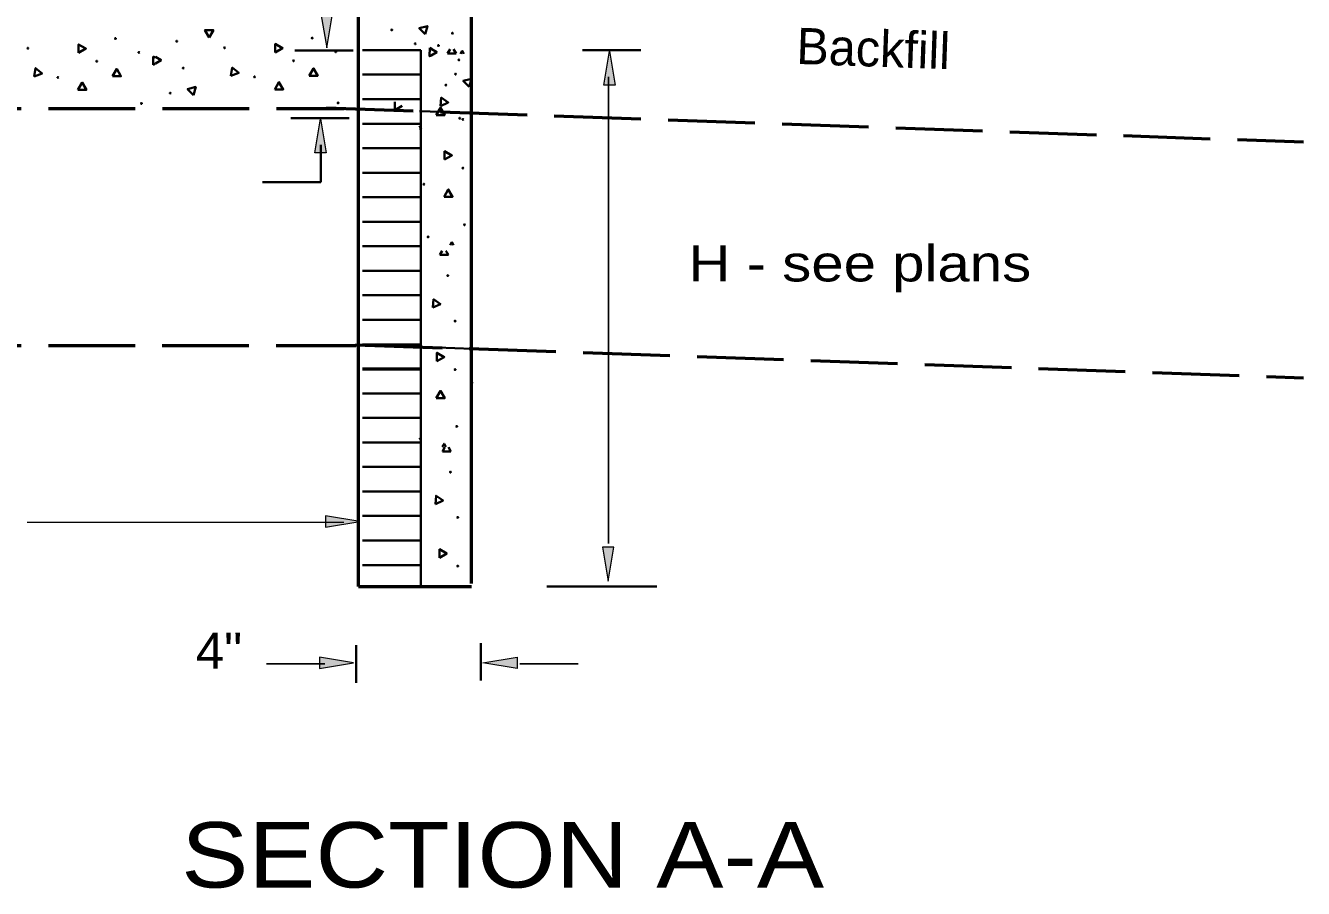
# Model space of a CAD drawing. Extents: x 72.6 to 107.3, y 36.1 to 58.1.
# Drawn here: x 92.859 to 97.548, y 50.456 to 53.623 of the extents above; entities that cross this region are included whole.
import ezdxf

# ---------------------------------------------------------------- set-up
doc = ezdxf.new("R2010")
doc.units = 0
doc.header["$LTSCALE"] = 0.053
doc.linetypes.add('LONG_DASHED', pattern=[7.5, 6, -1.5])
doc.layers.add('1', color=7, linetype='Continuous', lineweight=35)
doc.layers.add('3', color=7, linetype='Continuous', lineweight=13)

msp = doc.modelspace()

# ---------------------------------------------------------------- hatches: boundary and pattern name
at = {"layer": '3'}
for points in [[(93.98483, 53.66683), (93.94317, 53.66683), (93.964, 53.54183), (93.964, 53.54183)], [(95.02225, 53.40433), (94.98058, 53.40433), (95.00142, 53.52933), (95.00142, 53.52933)], [(93.962, 53.15625), (93.92033, 53.15625), (93.94117, 53.28125), (93.94117, 53.28125)], [(93.962, 53.15625), (93.92033, 53.15625), (93.94117, 53.28125), (93.94117, 53.28125)], [(93.96017, 51.82333), (93.96017, 51.78167), (94.08517, 51.8025), (94.08517, 51.8025)], [(93.96017, 51.82333), (93.96017, 51.78167), (94.08517, 51.8025), (94.08517, 51.8025)], [(95.01725, 51.70867), (94.97558, 51.70867), (94.99642, 51.58367), (94.99642, 51.58367)], [(95.01725, 51.70867), (94.97558, 51.70867), (94.99642, 51.58367), (94.99642, 51.58367)], [(93.93733, 51.30508), (93.93733, 51.26342), (94.06233, 51.28425), (94.06233, 51.28425)], [(93.93733, 51.30508), (93.93733, 51.26342), (94.06233, 51.28425), (94.06233, 51.28425)], [(94.6625, 51.30508), (94.6625, 51.26342), (94.5375, 51.28425), (94.5375, 51.28425)], [(94.6625, 51.30508), (94.6625, 51.26342), (94.5375, 51.28425), (94.5375, 51.28425)]]:
    msp.add_hatch(color=256, dxfattribs=at).paths.add_polyline_path(points)

# ---------------------------------------------------------------- linework, layer by layer
at = {"layer": '1', "lineweight": 53}
for p, q in [((94.08108, 51.56458), (94.08108, 54.64367)), ((94.49525, 51.575), (94.49525, 54.62758)), ((94.49525, 51.575), (94.49525, 54.20483)), ((94.49525, 51.575), (94.49525, 54.20483)), ((94.09533, 52.36308), (94.30925, 52.36308)), ((94.08108, 51.56458), (94.49525, 51.56458))]:
    msp.add_line(p, q, dxfattribs=at)
at = {"layer": '1'}
for p, q in [((93.328, 53.50992), (93.32783, 53.47883)), ((93.328, 53.50992), (93.32783, 53.47883)), ((93.328, 53.50992), (93.32783, 53.47883)), ((93.328, 53.50992), (93.32783, 53.47883)), ((93.33417, 53.50633), (93.328, 53.50992)), ((93.33417, 53.50633), (93.328, 53.50992)), ((93.33417, 53.50633), (93.328, 53.50992)), ((93.33417, 53.50633), (93.328, 53.50992)), ((94.06092, 53.53192), (93.847, 53.53192)), ((94.09533, 53.53308), (94.30925, 53.53308)), ((94.09533, 53.53308), (94.17508, 53.53308)), ((94.09533, 53.53308), (94.17508, 53.53308)), ((94.30925, 51.56458), (94.30925, 53.53308)), ((94.30925, 51.56458), (94.30925, 53.53308)), ((94.30925, 51.56458), (94.30925, 53.53308)), ((94.342, 53.5415), (94.34183, 53.51042)), ((94.342, 53.5415), (94.34183, 53.51042)), ((94.34183, 53.51042), (94.34817, 53.514)), ((94.34183, 53.51042), (94.34817, 53.514)), ((94.34817, 53.53792), (94.342, 53.5415)), ((94.34817, 53.53792), (94.342, 53.5415)), ((94.34817, 53.53792), (94.342, 53.5415)), ((94.34817, 53.53792), (94.342, 53.5415)), ((94.41667, 53.53667), (94.40767, 53.52125)), ((94.41667, 53.53667), (94.40767, 53.52125)), ((94.41667, 53.53667), (94.40767, 53.52125)), ((94.41667, 53.53667), (94.40767, 53.52125)), ((94.40767, 53.52125), (94.43883, 53.52125)), ((94.40767, 53.52125), (94.43883, 53.52125)), ((94.40767, 53.52125), (94.43883, 53.52125)), ((94.40767, 53.52125), (94.43883, 53.52125)), ((94.43883, 53.52125), (94.42983, 53.53667)), ((94.43883, 53.52125), (94.42983, 53.53667)), ((94.43883, 53.52125), (94.42983, 53.53667)), ((94.43883, 53.52125), (94.42983, 53.53667)), ((95.11617, 53.533), (94.90225, 53.533)), ((93.32783, 53.47883), (93.33417, 53.48242)), ((93.32783, 53.47883), (93.33417, 53.48242)), ((93.32783, 53.47883), (93.33417, 53.48242)), ((93.32783, 53.47883), (93.33417, 53.48242)), ((94.09533, 53.44308), (94.30925, 53.44308)), ((94.09533, 53.35308), (94.30925, 53.35308)), ((94.21458, 53.34367), (94.21433, 53.31267)), ((94.21458, 53.34367), (94.21433, 53.31267)), ((94.21433, 53.31267), (94.24133, 53.32817)), ((94.21433, 53.31267), (94.24133, 53.32817)), ((94.04617, 53.28375), (93.83225, 53.28375)), ((94.09533, 53.26308), (94.30925, 53.26308)), ((94.30417, 53.26308), (94.30925, 53.26308)), ((94.30417, 53.26308), (94.30925, 53.26308)), ((94.09533, 53.17308), (94.30925, 53.17308)), ((94.30417, 53.17308), (94.30925, 53.17308)), ((94.30417, 53.17308), (94.30925, 53.17308)), ((94.09533, 53.08308), (94.30925, 53.08308)), ((94.30417, 53.08308), (94.30925, 53.08308)), ((94.30417, 53.08308), (94.30925, 53.08308)), ((93.94267, 53.04792), (93.72875, 53.04792)), ((94.09533, 52.99308), (94.30925, 52.99308)), ((94.30417, 52.99308), (94.30925, 52.99308)), ((94.30417, 52.99308), (94.30925, 52.99308)), ((94.09533, 52.90308), (94.30925, 52.90308)), ((94.30417, 52.90308), (94.30925, 52.90308)), ((94.30417, 52.90308), (94.30925, 52.90308)), ((94.09533, 52.81308), (94.30925, 52.81308)), ((94.30417, 52.81308), (94.30925, 52.81308)), ((94.30417, 52.81308), (94.30925, 52.81308)), ((94.38825, 52.79658), (94.37925, 52.78117)), ((94.38825, 52.79658), (94.37925, 52.78117)), ((94.41042, 52.78117), (94.40142, 52.79658)), ((94.41042, 52.78117), (94.40142, 52.79658)), ((94.37925, 52.78117), (94.41042, 52.78117)), ((94.37925, 52.78117), (94.41042, 52.78117)), ((94.37925, 52.78117), (94.41042, 52.78117)), ((94.37925, 52.78117), (94.41042, 52.78117)), ((94.09533, 52.72308), (94.30925, 52.72308)), ((94.30417, 52.72308), (94.30925, 52.72308)), ((94.30417, 52.72308), (94.30925, 52.72308)), ((94.09533, 52.63308), (94.30925, 52.63308)), ((94.30417, 52.63308), (94.30925, 52.63308)), ((94.30417, 52.63308), (94.30925, 52.63308)), ((94.09533, 52.54308), (94.30925, 52.54308)), ((94.30417, 52.54308), (94.30925, 52.54308)), ((94.30417, 52.54308), (94.30925, 52.54308)), ((94.09533, 52.45308), (94.30925, 52.45308)), ((94.30417, 52.45308), (94.30925, 52.45308)), ((94.30417, 52.45308), (94.30925, 52.45308)), ((94.30417, 52.36308), (94.30925, 52.36308)), ((94.30417, 52.36308), (94.30925, 52.36308)), ((94.49858, 52.31492), (94.49308, 52.30542)), ((94.49858, 52.31492), (94.49308, 52.30542)), ((94.49308, 52.30542), (94.49858, 52.30542)), ((94.49308, 52.30542), (94.49858, 52.30542)), ((94.09533, 52.27308), (94.30925, 52.27308)), ((94.30417, 52.27308), (94.30925, 52.27308)), ((94.30417, 52.27308), (94.30925, 52.27308)), ((94.36633, 52.25508), (94.39742, 52.25508)), ((94.36633, 52.25508), (94.39742, 52.25508)), ((94.09533, 52.18308), (94.30925, 52.18308)), ((94.30417, 52.18308), (94.30925, 52.18308)), ((94.30417, 52.18308), (94.30925, 52.18308)), ((94.09533, 52.09308), (94.30925, 52.09308)), ((94.30417, 52.09308), (94.30925, 52.09308)), ((94.30417, 52.09308), (94.30925, 52.09308)), ((94.39775, 52.07542), (94.38875, 52.06)), ((94.39775, 52.07542), (94.38875, 52.06)), ((94.39775, 52.07542), (94.38875, 52.06)), ((94.39775, 52.07542), (94.38875, 52.06)), ((94.38875, 52.06), (94.41992, 52.06)), ((94.38875, 52.06), (94.41992, 52.06)), ((94.38875, 52.06), (94.41992, 52.06)), ((94.38875, 52.06), (94.41992, 52.06)), ((94.41992, 52.06), (94.41092, 52.07542)), ((94.41992, 52.06), (94.41092, 52.07542)), ((94.41992, 52.06), (94.41092, 52.07542)), ((94.41992, 52.06), (94.41092, 52.07542)), ((94.09533, 52.00308), (94.30925, 52.00308)), ((94.30417, 52.00308), (94.30925, 52.00308)), ((94.30417, 52.00308), (94.30925, 52.00308)), ((94.09533, 51.91308), (94.30925, 51.91308)), ((94.30417, 51.91308), (94.30925, 51.91308)), ((94.30417, 51.91308), (94.30925, 51.91308)), ((94.09533, 51.82308), (94.30925, 51.82308)), ((94.30417, 51.82308), (94.30925, 51.82308)), ((94.30417, 51.82308), (94.30925, 51.82308)), ((94.09533, 51.73308), (94.30925, 51.73308)), ((94.30417, 51.73308), (94.30925, 51.73308)), ((94.30417, 51.73308), (94.30925, 51.73308)), ((94.09533, 51.64308), (94.30925, 51.64308)), ((94.30417, 51.64308), (94.30925, 51.64308)), ((94.30417, 51.64308), (94.30925, 51.64308)), ((94.30417, 51.56458), (94.4065, 51.56458)), ((94.30417, 51.56458), (94.4065, 51.56458)), ((95.17558, 51.56458), (94.77183, 51.56458)), ((95.17558, 51.56458), (94.77183, 51.56458))]:
    msp.add_line(p, q, dxfattribs=at)
at = {"layer": '1', "linetype": 'LONG_DASHED', "lineweight": 53}
for p, q in [((90.01767, 53.31908), (94.0285, 53.31908)), ((90.01767, 53.31908), (94.0285, 53.31908)), ((93.96375, 53.32133), (97.54775, 53.19617)), ((90.017, 52.44892), (94.07125, 52.44892)), ((94.06967, 52.45192), (97.54775, 52.3305))]:
    msp.add_line(p, q, dxfattribs=at)
at = {"layer": '1', "linetype": 'LONG_DASHED'}
for p, q in [((94.30417, 53.30942), (94.49858, 53.30267)), ((94.30417, 53.30942), (94.49858, 53.30267)), ((94.30417, 52.44375), (94.49858, 52.43692)), ((94.30417, 52.44375), (94.49858, 52.43692))]:
    msp.add_line(p, q, dxfattribs=at)
at = {"layer": '1', "lineweight": 25}
for p, q in [((93.94267, 53.04792), (93.72875, 53.04792)), ((93.95708, 51.28083), (93.74317, 51.28083)), ((93.95708, 51.28083), (93.74317, 51.28083)), ((94.8865, 51.28083), (94.67258, 51.28083)), ((94.8865, 51.28083), (94.67258, 51.28083))]:
    msp.add_line(p, q, dxfattribs=at)
at = {"layer": '1'}
for points in [[(93.53308, 53.57967), (93.54867, 53.60658), (93.51758, 53.60658)], [(93.53308, 53.57967), (93.54867, 53.60658), (93.51758, 53.60658)], [(93.53308, 53.57967), (93.54867, 53.60658), (93.51758, 53.60658)], [(93.53308, 53.57967), (93.54867, 53.60658), (93.51758, 53.60658)], [(94.32542, 53.59133), (94.33342, 53.62142), (94.3035, 53.61342)], [(94.32542, 53.59133), (94.33342, 53.62142), (94.3035, 53.61342)], [(94.32542, 53.59133), (94.33342, 53.62142), (94.3035, 53.61342)], [(94.32542, 53.59133), (94.33342, 53.62142), (94.3035, 53.61342)], [(93.05367, 53.523), (93.08058, 53.5385), (93.05375, 53.55408)], [(93.05367, 53.523), (93.08058, 53.5385), (93.05375, 53.55408)], [(93.7755, 53.52492), (93.80242, 53.54042), (93.77558, 53.556)], [(93.7755, 53.52492), (93.80242, 53.54042), (93.77558, 53.556)], [(93.7755, 53.52492), (93.80242, 53.54042), (93.77558, 53.556)], [(93.7755, 53.52492), (93.80242, 53.54042), (93.77558, 53.556)], [(92.89058, 53.43675), (92.91975, 53.44742), (92.896, 53.46725)], [(92.89058, 53.43675), (92.91975, 53.44742), (92.896, 53.46725)], [(93.17833, 53.43742), (93.20933, 53.43742), (93.19392, 53.46425)], [(93.17833, 53.43742), (93.20933, 53.43742), (93.19392, 53.46425)], [(93.61242, 53.43867), (93.64158, 53.44933), (93.61783, 53.46917)], [(93.61242, 53.43867), (93.64158, 53.44933), (93.61783, 53.46917)], [(93.61242, 53.43867), (93.64158, 53.44933), (93.61783, 53.46917)], [(93.61242, 53.43867), (93.64158, 53.44933), (93.61783, 53.46917)], [(93.90017, 53.43933), (93.93117, 53.43933), (93.91575, 53.46617)], [(93.90017, 53.43933), (93.93117, 53.43933), (93.91575, 53.46617)], [(93.90017, 53.43933), (93.93117, 53.43933), (93.91575, 53.46617)], [(93.90017, 53.43933), (93.93117, 53.43933), (93.91575, 53.46617)], [(93.05158, 53.38708), (93.08267, 53.38708), (93.06717, 53.41392)], [(93.05158, 53.38708), (93.08267, 53.38708), (93.06717, 53.41392)], [(93.77342, 53.389), (93.8045, 53.389), (93.789, 53.41583)], [(93.77342, 53.389), (93.8045, 53.389), (93.789, 53.41583)], [(93.77342, 53.389), (93.8045, 53.389), (93.789, 53.41583)], [(93.77342, 53.389), (93.8045, 53.389), (93.789, 53.41583)], [(94.48725, 53.398), (94.49525, 53.428), (94.46533, 53.42)], [(94.48725, 53.398), (94.49525, 53.428), (94.46533, 53.42)], [(93.47592, 53.36833), (93.48392, 53.39833), (93.454, 53.39033)], [(93.47592, 53.36833), (93.48392, 53.39833), (93.454, 53.39033)], [(93.47592, 53.36833), (93.48392, 53.39833), (93.454, 53.39033)], [(93.47592, 53.36833), (93.48392, 53.39833), (93.454, 53.39033)], [(94.38167, 53.32792), (94.40983, 53.341), (94.3845, 53.35883)], [(94.38167, 53.32792), (94.40983, 53.341), (94.3845, 53.35883)], [(94.38167, 53.32792), (94.40983, 53.341), (94.3845, 53.35883)], [(94.38167, 53.32792), (94.40983, 53.341), (94.3845, 53.35883)], [(94.36617, 53.2945), (94.39725, 53.2945), (94.38183, 53.32133)], [(94.36617, 53.2945), (94.39725, 53.2945), (94.38183, 53.32133)], [(94.39683, 53.13108), (94.42375, 53.14658), (94.39692, 53.16217)], [(94.39683, 53.13108), (94.42375, 53.14658), (94.39692, 53.16217)], [(94.39683, 53.13108), (94.42375, 53.14658), (94.39692, 53.16217)], [(94.39683, 53.13108), (94.42375, 53.14658), (94.39692, 53.16217)], [(94.39475, 52.99517), (94.42583, 52.99517), (94.41033, 53.022)], [(94.39475, 52.99517), (94.42583, 52.99517), (94.41033, 53.022)], [(94.39475, 52.99517), (94.42583, 52.99517), (94.41033, 53.022)], [(94.39475, 52.99517), (94.42583, 52.99517), (94.41033, 53.022)], [(94.35325, 52.58783), (94.38142, 52.60092), (94.35608, 52.61875)], [(94.35325, 52.58783), (94.38142, 52.60092), (94.35608, 52.61875)], [(94.35325, 52.58783), (94.38142, 52.60092), (94.35608, 52.61875)], [(94.35325, 52.58783), (94.38142, 52.60092), (94.35608, 52.61875)], [(94.36842, 52.391), (94.39533, 52.4065), (94.3685, 52.42208)], [(94.36842, 52.391), (94.39533, 52.4065), (94.3685, 52.42208)], [(94.36842, 52.391), (94.39533, 52.4065), (94.3685, 52.42208)], [(94.36842, 52.391), (94.39533, 52.4065), (94.3685, 52.42208)], [(94.36633, 52.25508), (94.39742, 52.25508), (94.38192, 52.28192)], [(94.36633, 52.25508), (94.39742, 52.25508), (94.38192, 52.28192)], [(94.36275, 51.86667), (94.39092, 51.87975), (94.36558, 51.89758)], [(94.36275, 51.86667), (94.39092, 51.87975), (94.36558, 51.89758)], [(94.36275, 51.86667), (94.39092, 51.87975), (94.36558, 51.89758)], [(94.36275, 51.86667), (94.39092, 51.87975), (94.36558, 51.89758)], [(94.37792, 51.66983), (94.40483, 51.68533), (94.378, 51.70092)], [(94.37792, 51.66983), (94.40483, 51.68533), (94.378, 51.70092)], [(94.37792, 51.66983), (94.40483, 51.68533), (94.378, 51.70092)], [(94.37792, 51.66983), (94.40483, 51.68533), (94.378, 51.70092)]]:
    msp.add_lwpolyline(points, close=True, dxfattribs=at)
for points in [[(93.336, 53.48433), (93.35658, 53.49633), (93.336, 53.50825)], [(93.336, 53.48433), (93.35658, 53.49633), (93.336, 53.50825)], [(93.336, 53.48433), (93.35658, 53.49633), (93.336, 53.50825)], [(93.336, 53.48433), (93.35658, 53.49633), (93.336, 53.50825)], [(94.342, 53.5415), (94.34183, 53.51042), (94.34817, 53.514)], [(94.342, 53.5415), (94.34183, 53.51042), (94.34817, 53.514)], [(94.34733, 53.514), (94.36792, 53.526), (94.34733, 53.53792)], [(94.34733, 53.514), (94.36792, 53.526), (94.34733, 53.53792)], [(94.46775, 53.51892), (94.46117, 53.53033), (94.45458, 53.51892)], [(94.46775, 53.51892), (94.46117, 53.53033), (94.45458, 53.51892)], [(94.46775, 53.51892), (94.46117, 53.53033), (94.45458, 53.51892)], [(94.46775, 53.51892), (94.46117, 53.53033), (94.45458, 53.51892)], [(94.30417, 53.2445), (94.31058, 53.2445), (94.30417, 53.25567)], [(94.30417, 53.2445), (94.31058, 53.2445), (94.30417, 53.25567)], [(94.30417, 53.2445), (94.31058, 53.2445), (94.30417, 53.25567)], [(94.30417, 53.2445), (94.31058, 53.2445), (94.30417, 53.25567)], [(94.42983, 52.81667), (94.42325, 52.82808), (94.41667, 52.81667)], [(94.42983, 52.81667), (94.42325, 52.82808), (94.41667, 52.81667)], [(94.42983, 52.81667), (94.42325, 52.82808), (94.41667, 52.81667)], [(94.42983, 52.81667), (94.42325, 52.82808), (94.41667, 52.81667)], [(94.40142, 52.07658), (94.39483, 52.088), (94.38825, 52.07658)], [(94.40142, 52.07658), (94.39483, 52.088), (94.38825, 52.07658)]]:
    msp.add_lwpolyline(points, dxfattribs=at)
for centre in [(94.20297, 53.60713), (94.20297, 53.60713), (94.42533, 53.59525), (94.42533, 53.59525), (93.18897, 53.57554), (93.18897, 53.57554), (93.414, 53.56558), (93.414, 53.56558), (93.414, 53.56558), (93.414, 53.56558), (93.5895, 53.54176), (93.5895, 53.54176), (93.5895, 53.54176), (93.5895, 53.54176), (93.9108, 53.57746), (93.9108, 53.57746), (93.9108, 53.57746), (93.9108, 53.57746), (94.28925, 53.55655), (94.28925, 53.55655), (94.37373, 53.5497), (94.37373, 53.5497), (94.37373, 53.5497), (94.37373, 53.5497), (92.86767, 53.53984), (92.86767, 53.53984), (93.27525, 53.52496), (93.27525, 53.52496), (93.8424, 53.49418), (93.8424, 53.49418), (93.8424, 53.49418), (93.8424, 53.49418), (93.99708, 53.52688), (93.99708, 53.52688), (93.99708, 53.52688), (93.99708, 53.52688), (94.44909, 53.49709), (94.44909, 53.49709), (93.12057, 53.49226), (93.12057, 53.49226), (93.43776, 53.46742), (93.43776, 53.46742), (93.43776, 53.46742), (93.43776, 53.46742), (92.97777, 53.43274), (92.97777, 53.43274), (93.6996, 53.43466), (93.6996, 53.43466), (93.6996, 53.43466), (93.6996, 53.43466), (94.40151, 53.40487), (94.40151, 53.40487), (94.43691, 53.44547), (94.43691, 53.44547), (94.43691, 53.44547), (94.43691, 53.44547), (93.39018, 53.3752), (93.39018, 53.3752), (93.39018, 53.3752), (93.39018, 53.3752), (93.28419, 53.33758), (93.28419, 53.33758), (94.00602, 53.3395), (94.00602, 53.3395), (94.00602, 53.3395), (94.00602, 53.3395), (94.45209, 53.28289), (94.45209, 53.28289), (94.46373, 53.27885), (94.46373, 53.27885), (94.46373, 53.27885), (94.46373, 53.27885), (94.46373, 53.10035), (94.46373, 53.10035), (94.46373, 53.10035), (94.46373, 53.10035), (94.32093, 53.04083), (94.32093, 53.04083), (94.32093, 53.04083), (94.32093, 53.04083), (94.46967, 52.89209), (94.46967, 52.89209), (94.46967, 52.89209), (94.46967, 52.89209), (94.33581, 52.84745), (94.33581, 52.84745), (94.33581, 52.84745), (94.33581, 52.84745), (94.4085, 52.70538), (94.4085, 52.70538), (94.43532, 52.53876), (94.43532, 52.53876), (94.43532, 52.36026), (94.43532, 52.36026), (94.44126, 52.152), (94.44126, 52.152), (94.3074, 52.10736), (94.3074, 52.10736), (94.418, 51.98422), (94.418, 51.98422), (94.418, 51.98422), (94.418, 51.98422), (94.44482, 51.8176), (94.44482, 51.8176), (94.44482, 51.8176), (94.44482, 51.8176), (94.44482, 51.6391), (94.44482, 51.6391), (94.44482, 51.6391), (94.44482, 51.6391)]:
    msp.add_circle(centre, 0.00173, dxfattribs=at)
at = {"layer": '3', "lineweight": 25}
for p, q in [((94.99792, 53.43475), (94.99792, 51.72208)), ((93.94267, 53.18533), (93.94267, 53.04792))]:
    msp.add_line(p, q, dxfattribs=at)
at = {"layer": '3', "lineweight": 35}
for p, q in [((93.94267, 53.18533), (93.94267, 53.04792)), ((94.07217, 51.3485), (94.07217, 51.21108)), ((94.07217, 51.3485), (94.07217, 51.21108)), ((94.52933, 51.35608), (94.52933, 51.21867)), ((94.52933, 51.35608), (94.52933, 51.21867))]:
    msp.add_line(p, q, dxfattribs=at)
at = {"layer": '3'}
msp.add_line((92.86525, 51.80017), (94.0275, 51.80017), dxfattribs=at)
msp.add_line((92.86525, 51.80017), (94.0275, 51.80017), dxfattribs=at)
for points in [[(93.98483, 53.66683), (93.94317, 53.66683), (93.964, 53.54183), (93.964, 53.54183)], [(95.02225, 53.40433), (94.98058, 53.40433), (95.00142, 53.52933), (95.00142, 53.52933)], [(93.962, 53.15625), (93.92033, 53.15625), (93.94117, 53.28125), (93.94117, 53.28125)], [(93.962, 53.15625), (93.92033, 53.15625), (93.94117, 53.28125), (93.94117, 53.28125)], [(93.96017, 51.82333), (93.96017, 51.78167), (94.08517, 51.8025), (94.08517, 51.8025)], [(93.96017, 51.82333), (93.96017, 51.78167), (94.08517, 51.8025), (94.08517, 51.8025)], [(95.01725, 51.70867), (94.97558, 51.70867), (94.99642, 51.58367), (94.99642, 51.58367)], [(95.01725, 51.70867), (94.97558, 51.70867), (94.99642, 51.58367), (94.99642, 51.58367)], [(93.93733, 51.30508), (93.93733, 51.26342), (94.06233, 51.28425), (94.06233, 51.28425)], [(93.93733, 51.30508), (93.93733, 51.26342), (94.06233, 51.28425), (94.06233, 51.28425)], [(94.6625, 51.30508), (94.6625, 51.26342), (94.5375, 51.28425), (94.5375, 51.28425)], [(94.6625, 51.30508), (94.6625, 51.26342), (94.5375, 51.28425), (94.5375, 51.28425)]]:
    msp.add_lwpolyline(points, close=True, dxfattribs=at)

# ---------------------------------------------------------------- texts
msp.add_text('Backfill', height=0.133, rotation=358, dxfattribs=at).set_placement((95.686, 53.48267))
for s, height, width, p in [('H - see plans', 0.133, 1.2, (95.29158, 52.684)), ('4"', 0.133, 1.05, (93.48383, 51.26208)), ('4"', 0.133, 1.05, (93.48383, 51.26208)), ('SECTION A-A', 0.24, 1.15, (93.43042, 50.45917))]:
    msp.add_text(s, height=height, dxfattribs=dict(at, width=width)).set_placement(p)

doc.saveas('drawing.dxf')
